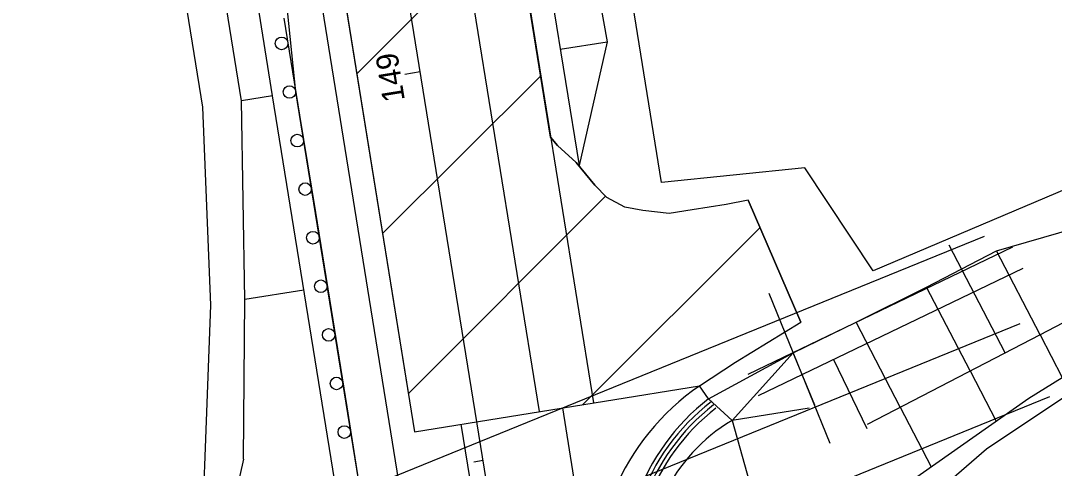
# Model space of a CAD drawing. Extents: x 195197 to 195502, y 336876 to 337459.
# Drawn here: x 195268.9 to 195400.1, y 337180.8 to 337237.7 of the extents above; entities that cross this region are included whole.
import ezdxf

# ---------------------------------------------------------------- set-up
doc = ezdxf.new("R2010")
doc.units = 0
for name, color, linetype in [('_CIVIL_CONSTRUCTION', 7, 'Continuous'), ('DR_P_Cells', 7, 'Continuous'), ('DR_P_Headwall', 7, 'Continuous'), ('DT_X_Island', 7, 'Continuous'), ('DT_X_Void', 7, 'Continuous'), ('GK_Drainage_Nodes', 7, 'Continuous'), ('MD_P_Surface_Finished_Grade', 7, 'Continuous'), ('PV_P_Shoulder', 7, 'Continuous'), ('SC_Scratch1', 7, 'Continuous'), ('SH_Major_Grid_Line', 7, 'Continuous')]:
    doc.layers.add(name, color=color, linetype=linetype)

msp = doc.modelspace()

# ---------------------------------------------------------------- linework, layer by layer
at = {"layer": '_CIVIL_CONSTRUCTION'}
for points in [[(195415.16, 337192.63), (195427.5, 337191.06), (195439.23, 337196.72), (195449.47, 337204.35), (195456.27, 337211.36), (195462.31, 337228.75), (195456.54, 337236.65), (195437.52, 337231.22), (195415.54, 337222.22), (195377.07, 337205.9), (195368.38, 337218.99), (195350.22, 337217.12), (195339.28, 337284.98), (195322.46, 337307.59), (195306.55, 337406.32)], [(195287.97, 337251.38), (195291.95, 337226.7), (195292.97, 337201.54), (195292.2, 337181.16), (195292.01, 337176.07), (195280.02, 337163.48), (195272.33, 337157.95), (195268.88, 337148.33), (195288.8, 337131.36), (195292.54, 337124.96), (195302.23, 337099.91), (195307.11, 337075.58), (195321.43, 337052.24), (195341.13, 337030.76), (195347.82, 337006.27), (195355.4, 336981.71), (195364.48, 336957.43), (195370.64, 336943.15), (195384.3, 336949.34)], [(195378.92, 337164.76), (195379.72, 337173.14), (195391.45, 337183.27), (195402.66, 337190.8), (195415.16, 337192.63)]]:
    msp.add_lwpolyline(points, dxfattribs=at)
at = {"layer": 'DR_P_Cells'}
for p, q in [((195300.46, 337280.75), (195325.98, 337122.42)), ((195303.42, 337281.22), (195318.86, 337185.46)), ((195361.21, 337214.86), (195367.88, 337199.36)), ((195318.86, 337185.46), (195355.04, 337191.29))]:
    msp.add_line(p, q, dxfattribs=at)
msp.add_arc((195372.68, 337165.8), 31, 124.6664, 189.1784, dxfattribs=at)
at = {"layer": 'DR_P_Headwall'}
for p, q in [((195319.59, 337231.16), (195317.62, 337230.84)), ((195327.55, 337181.8), (195326.37, 337181.61))]:
    msp.add_line(p, q, dxfattribs=at)
at = {"layer": 'DT_X_Island'}
for p, q in [((195326.13, 337284.88), (195341.57, 337189.12)), ((195319.21, 337283.77), (195334.66, 337188.01))]:
    msp.add_line(p, q, dxfattribs=at)
at = {"layer": 'DT_X_Void'}
for p, q in [((195311.53, 337230.92), (195331.59, 337250.98)), ((195314.8, 337210.62), (195334.87, 337230.68)), ((195318.08, 337190.32), (195343.11, 337215.36)), ((195340.23, 337188.91), (195362.71, 337211.38))]:
    msp.add_line(p, q, dxfattribs=at)
msp.add_lwpolyline([(195303.42, 337281.22), (195318.86, 337185.46), (195355.04, 337191.29), (195359.61, 337194.28), (195367.88, 337199.36), (195361.21, 337214.86), (195358.41, 337214.3), (195354.09, 337213.65), (195351.19, 337213.17), (195347.82, 337213.57), (195345.55, 337214), (195343.28, 337215.19), (195341.72, 337216.77), (195339.39, 337219.66), (195337.01, 337221.81), (195336.13, 337222.85), (195326.13, 337284.88)], dxfattribs=at)
at = {"layer": 'GK_Drainage_Nodes'}
for p, q in [((195303.8, 337228.61), (195298.48, 337280.43)), ((195317.33, 337144.7), (195303.8, 337228.61)), ((195356.18, 337189.65), (195355.04, 337191.29))]:
    msp.add_line(p, q, dxfattribs=at)
msp.add_arc((195373.36, 337167.54), 28, 127.8475, 192.4752, dxfattribs=at)
at = {"layer": 'MD_P_Surface_Finished_Grade'}
for p, q in [((195302.29, 337237.99), (195304.28, 337225.65)), ((195304.28, 337225.65), (195306.27, 337213.31)), ((195306.27, 337213.31), (195308.26, 337200.97)), ((195308.26, 337200.97), (195310.25, 337188.63)), ((195310.25, 337188.63), (195312.23, 337176.29))]:
    msp.add_line(p, q, dxfattribs=at)
for centre in [(195301.99, 337234.78), (195302.99, 337228.61), (195303.98, 337222.44), (195304.98, 337216.27), (195305.97, 337210.1), (195306.97, 337203.93), (195307.96, 337197.76), (195308.96, 337191.59), (195309.95, 337185.42)]:
    msp.add_circle(centre, 0.8, dxfattribs=at)
at = {"layer": 'PV_P_Shoulder'}
for p, q in [((195300.84, 337228.14), (195292.88, 337277.5)), ((195338.99, 337259.61), (195343.29, 337234.98)), ((195333.39, 337258.71), (195339.74, 337219.26)), ((195296.89, 337227.5), (195292.91, 337252.18)), ((195337.36, 337234.03), (195343.29, 337234.98)), ((195343.29, 337234.98), (195339.74, 337219.26)), ((195300.84, 337228.14), (195296.89, 337227.5)), ((195314.37, 337144.22), (195300.84, 337228.14)), ((195297.34, 337202.25), (195296.89, 337227.5)), ((195392.71, 337208.43), (195402.51, 337211.27)), ((195383.84, 337203.83), (195392.71, 337208.43)), ((195398.24, 337197.78), (195392.71, 337208.43)), ((195304.82, 337203.45), (195297.34, 337202.25)), ((195374.89, 337199.36), (195383.84, 337203.83)), ((195389.37, 337193.18), (195383.84, 337203.83)), ((195297.16, 337181.96), (195297.34, 337202.25)), ((195407.12, 337202.39), (195398.24, 337197.78)), ((195366.92, 337195.49), (195374.89, 337199.36)), ((195380.49, 337188.57), (195374.89, 337199.36)), ((195398.24, 337197.78), (195376.28, 337186.38)), ((195398.24, 337197.78), (195401.06, 337192.36)), ((195356.18, 337189.65), (195366.92, 337195.49)), ((195359.15, 337186.89), (195366.92, 337195.49)), ((195369.64, 337188.82), (195366.92, 337195.49)), ((195389.37, 337193.18), (195392.67, 337186.82)), ((195396.8, 337189.71), (195401.06, 337192.36)), ((195356.18, 337189.65), (195359.15, 337186.89)), ((195375.39, 337174.7), (195396.8, 337189.71)), ((195380.49, 337188.57), (195384.41, 337181.02)), ((195368.92, 337188.47), (195359.15, 337186.89)), ((195359.15, 337186.89), (195365.48, 337164.5)), ((195297.16, 337181.96), (195295.99, 337176.71))]:
    msp.add_line(p, q, dxfattribs=at)
msp.add_arc((195370.48, 337167.83), 22.17, 120.7246, 187.1321, dxfattribs=at)
at = {"layer": 'SC_Scratch1'}
msp.add_line((195336.84, 337124.17), (195282.88, 337458.86), dxfattribs=at)
at = {"layer": 'SH_Major_Grid_Line'}
for p, q in [((195336.13, 337222.85), (195337.01, 337221.81)), ((195337.01, 337221.81), (195339.39, 337219.66)), ((195339.39, 337219.66), (195341.72, 337216.77)), ((195391.14, 337210.27), (195288.34, 337168.4)), ((195361.2, 337192.76), (195394.79, 337208.96)), ((195393.81, 337195.48), (195386.7, 337209.17)), ((195362.5, 337190.06), (195396.09, 337206.25)), ((195371.62, 337183.96), (195363.85, 337203.03)), ((195395.66, 337199.15), (195292.86, 337157.29)), ((195372.01, 337194.64), (195376.25, 337185.85)), ((195399.43, 337189.89), (195296.63, 337148.03)), ((195337.62, 337188.48), (195342.07, 337160.85)), ((195331.15, 337146.93), (195324.78, 337186.42))]:
    msp.add_line(p, q, dxfattribs=at)
for radius in [27.5, 27, 26.5]:
    msp.add_arc((195373.36, 337167.54), radius, 127.8475, 192.4752, dxfattribs=at)

# ---------------------------------------------------------------- texts
at = {"layer": 'DR_P_Headwall'}
msp.add_text('149', height=2.8, rotation=99.1593, dxfattribs=at).set_placement((195317.64, 337227.58))

doc.saveas('drawing.dxf')
